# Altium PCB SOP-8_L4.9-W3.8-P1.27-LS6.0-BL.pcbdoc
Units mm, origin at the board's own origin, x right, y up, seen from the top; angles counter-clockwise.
Board outline 18.01 x 20.32 mm, 2 copper layers (Top Layer, Bottom Layer), stack 0 mm thick; 1 components, 0 nets, 8 pads, 0 vias.
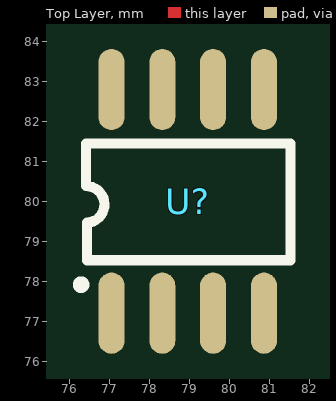
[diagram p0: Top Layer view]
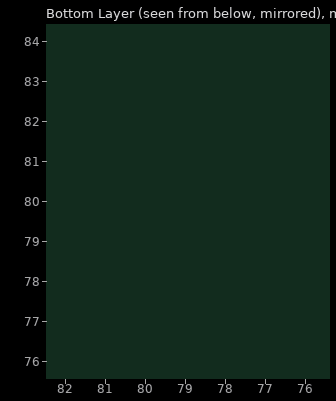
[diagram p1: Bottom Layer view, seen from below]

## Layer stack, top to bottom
Top Layer: signal copper (thickness not stored)
Bottom Layer: signal copper (thickness not stored)

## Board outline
87.863,69.85 69.85,69.85 69.85,90.174 87.863,90.174

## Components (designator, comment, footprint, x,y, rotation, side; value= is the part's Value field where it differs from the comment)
U? "" SOP-8_L4.9-W3.8-P1.27-LS6.0-BL 78.947,80.012 r0 top

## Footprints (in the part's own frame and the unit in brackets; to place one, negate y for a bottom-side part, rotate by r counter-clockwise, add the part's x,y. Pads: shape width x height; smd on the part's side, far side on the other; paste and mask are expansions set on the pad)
SOP-8_L4.9-W3.8-P1.27-LS6.0-BL [mm]
  oval 0.65x2.032 smd paste+0 mask+0.05: 1(-1.905,-2.796) 2(-0.635,-2.796) 3(0.635,-2.796) 4(1.905,-2.796) 5(1.905,2.796) 6(0.635,2.796) 7(-0.635,2.796) 8(-1.905,2.796)
  silkscreen extent -2.75,-2.16 2.57,1.45

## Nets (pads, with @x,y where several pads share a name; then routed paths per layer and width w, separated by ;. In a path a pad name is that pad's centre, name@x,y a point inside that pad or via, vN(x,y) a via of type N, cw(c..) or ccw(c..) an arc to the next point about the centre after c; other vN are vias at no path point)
pads on no net: U?.1 U?.2 U?.3 U?.4 U?.5 U?.6 U?.7 U?.8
